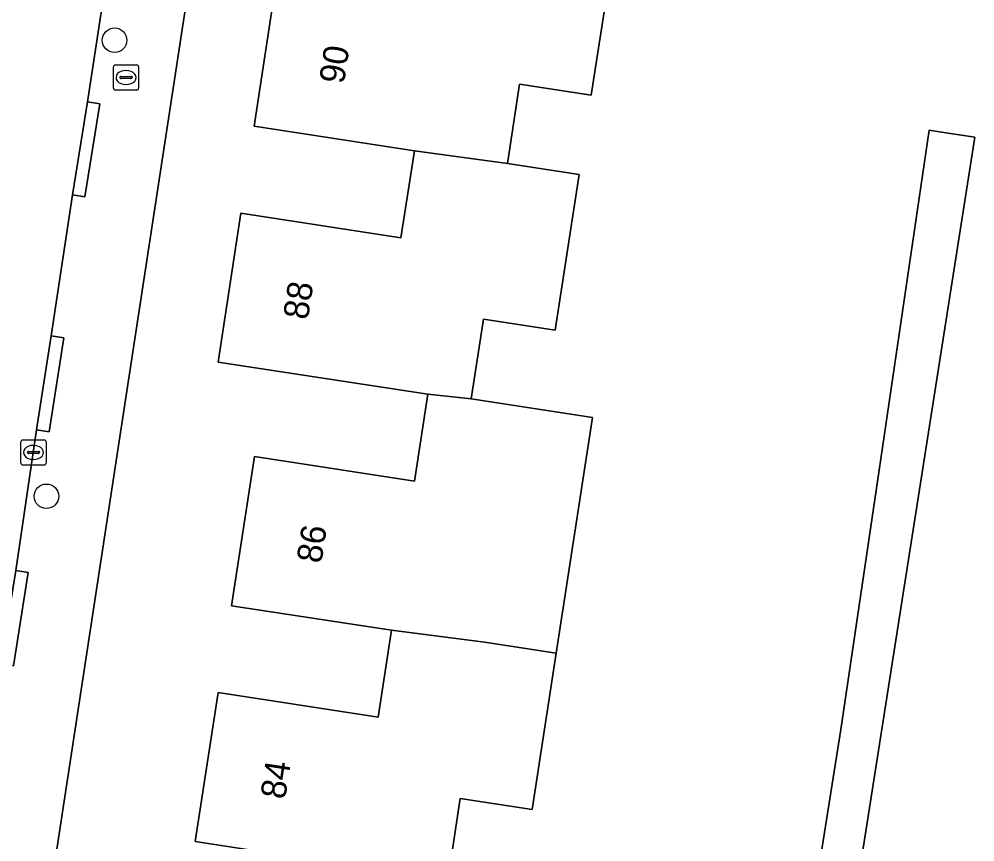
# Model space of a CAD drawing. Extents: x 161483 to 162250, y 379484 to 380833.
# Drawn here: x 161945.57 to 161983.61, y 380678.31 to 380711.06 of the extents above; entities that cross this region are included whole.
import ezdxf

# ---------------------------------------------------------------- set-up
doc = ezdxf.new("R2010")
doc.units = 0
for name, color, linetype in [('IMGEO_Boom', 7, 'Continuous'), ('IMGEO_Brandkraan', 7, 'Continuous'), ('IMGEO_Erf', 7, 'Continuous'), ('IMGEO_Kolk', 7, 'Continuous'), ('IMGEO_Pand', 7, 'Continuous'), ('IMGEO_Pand_nummerreeks', 7, 'Continuous'), ('IMGEO_Rijbaan_lokaal_open', 7, 'Continuous'), ('IMGEO_Voetpad_open', 7, 'Continuous')]:
    doc.layers.add(name, color=color, linetype=linetype)

msp = doc.modelspace()

# ---------------------------------------------------------------- linework, layer by layer
at = {"layer": 'IMGEO_Boom'}
for centre in [(161949.373, 380710.215), (161946.663, 380692.066)]:
    msp.add_circle(centre, 0.489, dxfattribs=at)
at = {"layer": 'IMGEO_Brandkraan'}
for p, q in [((161949.33, 380708.308), (161949.33, 380709.16)), ((161949.405, 380709.234), (161950.257, 380709.234)), ((161949.818, 380709.014), (161949.843, 380709.014)), ((161950.331, 380709.16), (161950.331, 380708.308)), ((161949.589, 380708.728), (161949.589, 380708.74)), ((161950.027, 380708.691), (161949.629, 380708.691)), ((161949.632, 380708.777), (161950.03, 380708.777)), ((161950.073, 380708.74), (161950.073, 380708.728)), ((161950.257, 380708.234), (161949.405, 380708.234)), ((161949.841, 380708.454), (161949.816, 380708.454))]:
    msp.add_line(p, q, dxfattribs=at)
for points in [[(161949.33, 380708.308), (161949.33, 380709.16)], [(161949.405, 380709.234), (161950.257, 380709.234)], [(161950.331, 380709.16), (161950.331, 380708.308)], [(161950.257, 380708.234), (161949.405, 380708.234)]]:
    msp.add_lwpolyline(points, dxfattribs=at)
for centre, radius, start, end in [((161949.407, 380709.158), 0.0765, 91.552, 178.448), ((161949.407, 380709.158), 0.0765, 91.552, 178.448), ((161950.255, 380709.158), 0.0765, 1.552, 88.448), ((161950.255, 380709.158), 0.0765, 1.552, 88.448), ((161949.629, 380708.737), 0.0403, 85.8775, 175.7526), ((161949.626, 380708.727), 0.0366, 178.938, 274.7102), ((161950.03, 380708.734), 0.043, 264.8664, 352.4533), ((161950.034, 380708.739), 0.0386, 1.7309, 96.639), ((161949.407, 380708.31), 0.0765, 181.552, 268.448), ((161949.407, 380708.31), 0.0765, 181.552, 268.448), ((161950.255, 380708.31), 0.0765, 271.552, 358.448), ((161950.255, 380708.31), 0.0765, 271.552, 358.448)]:
    msp.add_arc(centre, radius, start, end, dxfattribs=at)
for centre, major_axis, ratio, start_param, end_param in [((161949.817, 380708.734), (-0.387, 0.002), 0.722429, 4.712389, 7.853982), ((161949.842, 380708.734), (-0.39, 0.002), 0.717154, 1.570796, 4.712389)]:
    msp.add_ellipse(centre, major_axis=major_axis, ratio=ratio, start_param=start_param, end_param=end_param, dxfattribs=at)
at = {"layer": 'IMGEO_Erf'}
for points in [[(161955.311, 380731.889), (161949.611, 380694.604), (161942.94, 380651.025), (161940.472, 380634.904), (161938.44, 380621.627), (161934.347, 380594.923)], [(161969.304, 380714.255), (161968.345, 380708.025), (161965.492, 380708.464), (161965.007, 380705.315), (161967.86, 380704.875), (161966.905, 380698.675), (161964.052, 380699.114), (161963.564, 380695.945), (161968.393, 380695.202), (161967.439, 380689.011), (161966.949, 380685.822), (161965.991, 380679.602), (161963.128, 380680.042), (161962.65, 380676.871)], [(161958.957, 380677.351), (161952.586, 380678.33), (161953.496, 380684.256), (161959.867, 380683.277), (161960.398, 380686.734), (161954.027, 380687.713), (161954.94, 380693.65), (161961.31, 380692.671), (161961.84, 380696.13), (161953.49, 380697.41), (161954.401, 380703.335), (161960.77, 380702.355), (161961.302, 380705.811), (161954.932, 380706.791), (161955.83, 380712.72)], [(161975.782, 380667.07), (161978.273, 380682.786), (161979.804, 380693.104), (161981.795, 380706.637), (161982.278, 380706.561), (161983.609, 380706.352), (161977.569, 380667.933)]]:
    msp.add_lwpolyline(points, dxfattribs=at)
at = {"layer": 'IMGEO_Kolk'}
for p, q in [((161945.645, 380693.385), (161945.645, 380694.237)), ((161945.72, 380694.311), (161946.572, 380694.311)), ((161946.133, 380694.091), (161946.158, 380694.091)), ((161946.646, 380694.237), (161946.646, 380693.385)), ((161945.904, 380693.805), (161945.904, 380693.817)), ((161946.342, 380693.768), (161945.944, 380693.768)), ((161945.947, 380693.854), (161946.345, 380693.854)), ((161946.388, 380693.817), (161946.388, 380693.805)), ((161946.572, 380693.311), (161945.72, 380693.311)), ((161946.156, 380693.531), (161946.131, 380693.531))]:
    msp.add_line(p, q, dxfattribs=at)
for points in [[(161945.645, 380693.385), (161945.645, 380694.237)], [(161945.72, 380694.311), (161946.572, 380694.311)], [(161946.646, 380694.237), (161946.646, 380693.385)], [(161946.572, 380693.311), (161945.72, 380693.311)]]:
    msp.add_lwpolyline(points, dxfattribs=at)
for centre, radius, start, end in [((161945.722, 380694.235), 0.0765, 91.552, 178.448), ((161945.722, 380694.235), 0.0765, 91.552, 178.448), ((161946.57, 380694.235), 0.0765, 1.552, 88.448), ((161946.57, 380694.235), 0.0765, 1.552, 88.448), ((161945.944, 380693.814), 0.0403, 85.8775, 175.7526), ((161945.941, 380693.804), 0.0366, 178.938, 274.7102), ((161946.345, 380693.811), 0.043, 264.8664, 352.4533), ((161946.349, 380693.816), 0.0386, 1.7309, 96.639), ((161945.722, 380693.387), 0.0765, 181.552, 268.448), ((161945.722, 380693.387), 0.0765, 181.552, 268.448), ((161946.57, 380693.387), 0.0765, 271.552, 358.448), ((161946.57, 380693.387), 0.0765, 271.552, 358.448)]:
    msp.add_arc(centre, radius, start, end, dxfattribs=at)
for centre, major_axis, ratio, start_param, end_param in [((161946.132, 380693.811), (-0.387, 0.002), 0.722429, 4.712389, 7.853982), ((161946.157, 380693.811), (-0.39, 0.002), 0.717154, 1.570796, 4.712389)]:
    msp.add_ellipse(centre, major_axis=major_axis, ratio=ratio, start_param=start_param, end_param=end_param, dxfattribs=at)
at = {"layer": 'IMGEO_Pand'}
for points in [[(161961.302, 380705.811), (161965.007, 380705.315), (161965.492, 380708.464), (161968.345, 380708.025), (161969.304, 380714.255), (161962.749, 380715.223), (161962.213, 380711.737), (161955.83, 380712.72), (161954.932, 380706.791)], [(161961.302, 380705.811), (161960.77, 380702.355), (161954.401, 380703.335), (161953.49, 380697.41), (161961.84, 380696.13), (161963.564, 380695.945), (161964.052, 380699.114), (161966.905, 380698.675), (161967.86, 380704.875), (161965.007, 380705.315)], [(161968.393, 380695.202), (161963.564, 380695.945), (161961.84, 380696.13), (161961.31, 380692.671), (161954.94, 380693.65), (161954.027, 380687.713), (161960.398, 380686.734), (161964.095, 380686.261), (161966.949, 380685.822), (161967.439, 380689.011)], [(161958.957, 380677.351), (161962.65, 380676.871), (161963.128, 380680.042), (161965.991, 380679.602), (161966.949, 380685.822), (161964.095, 380686.261), (161960.398, 380686.734), (161959.867, 380683.277), (161953.496, 380684.256), (161952.586, 380678.33)]]:
    msp.add_lwpolyline(points, close=True, dxfattribs=at)
at = {"layer": 'IMGEO_Rijbaan_lokaal_open'}
for points in [[(161947.699, 380704.067), (161948.294, 380707.766), (161949.178, 380713.594), (161949.75, 380717.326), (161950.566, 380722.765), (161951.16, 380726.486), (161951.552, 380729.165)], [(161937.052, 380634.637), (161937.178, 380635.427), (161937.574, 380637.901), (161938.771, 380645.995), (161939.351, 380649.714), (161940.513, 380657.293), (161941.106, 380660.987), (161941.964, 380666.501), (161942.538, 380670.221), (161943.378, 380676.03), (161943.976, 380679.748), (161944.852, 380685.403), (161945.442, 380689.115), (161946.272, 380694.705), (161946.856, 380698.453), (161947.699, 380704.067)]]:
    msp.add_lwpolyline(points, dxfattribs=at)
at = {"layer": 'IMGEO_Voetpad_open'}
for points in [[(161927.166, 380621.505), (161926.845, 380619.322), (161927.469, 380619.219), (161932.392, 380618.524), (161932.982, 380622.467), (161938.44, 380621.627), (161940.472, 380634.904), (161942.94, 380651.025), (161949.611, 380694.604), (161955.311, 380731.889)], [(161951.552, 380729.165), (161951.16, 380726.486), (161951.653, 380726.408), (161951.059, 380722.687), (161950.566, 380722.765), (161949.75, 380717.326), (161950.244, 380717.251), (161949.672, 380713.519), (161949.178, 380713.594), (161948.294, 380707.766), (161948.787, 380707.687), (161948.192, 380703.988), (161947.699, 380704.067), (161946.856, 380698.453), (161947.35, 380698.377), (161946.766, 380694.629), (161946.272, 380694.705), (161945.442, 380689.115), (161945.935, 380689.037), (161945.345, 380685.325)]]:
    msp.add_lwpolyline(points, dxfattribs=at)
for points in [[(161948.294, 380707.766), (161947.699, 380704.067), (161948.192, 380703.988), (161948.787, 380707.687)], [(161983.609, 380706.352), (161982.278, 380706.561), (161981.795, 380706.637), (161979.804, 380693.104), (161978.273, 380682.786), (161975.782, 380667.07), (161976.056, 380667.027), (161981.895, 380666.109), (161982.08, 380667.223), (161977.569, 380667.933)], [(161946.856, 380698.453), (161946.272, 380694.705), (161946.766, 380694.629), (161947.35, 380698.377)], [(161945.442, 380689.115), (161944.852, 380685.403), (161945.345, 380685.325), (161945.935, 380689.037)]]:
    msp.add_lwpolyline(points, close=True, dxfattribs=at)

# ---------------------------------------------------------------- texts
at = {"layer": 'IMGEO_Pand_nummerreeks'}
for s, rotation, p in [('90', 81.3875, (161958.5, 380708.45)), ('88', 81.2589, (161957.063, 380699.06)), ('86', 81.2569, (161957.6, 380689.366)), ('84', 81.2698, (161956.158, 380679.978))]:
    msp.add_text(s, height=1, rotation=rotation, dxfattribs=at).set_placement(p)

doc.saveas('drawing.dxf')
